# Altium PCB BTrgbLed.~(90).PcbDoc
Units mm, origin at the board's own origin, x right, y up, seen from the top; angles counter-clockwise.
Board outline 98.71 x 98.67 mm, 2 copper layers (Top Layer, Bottom Layer); 15 components, 12 nets, 66 pads, 7 vias.
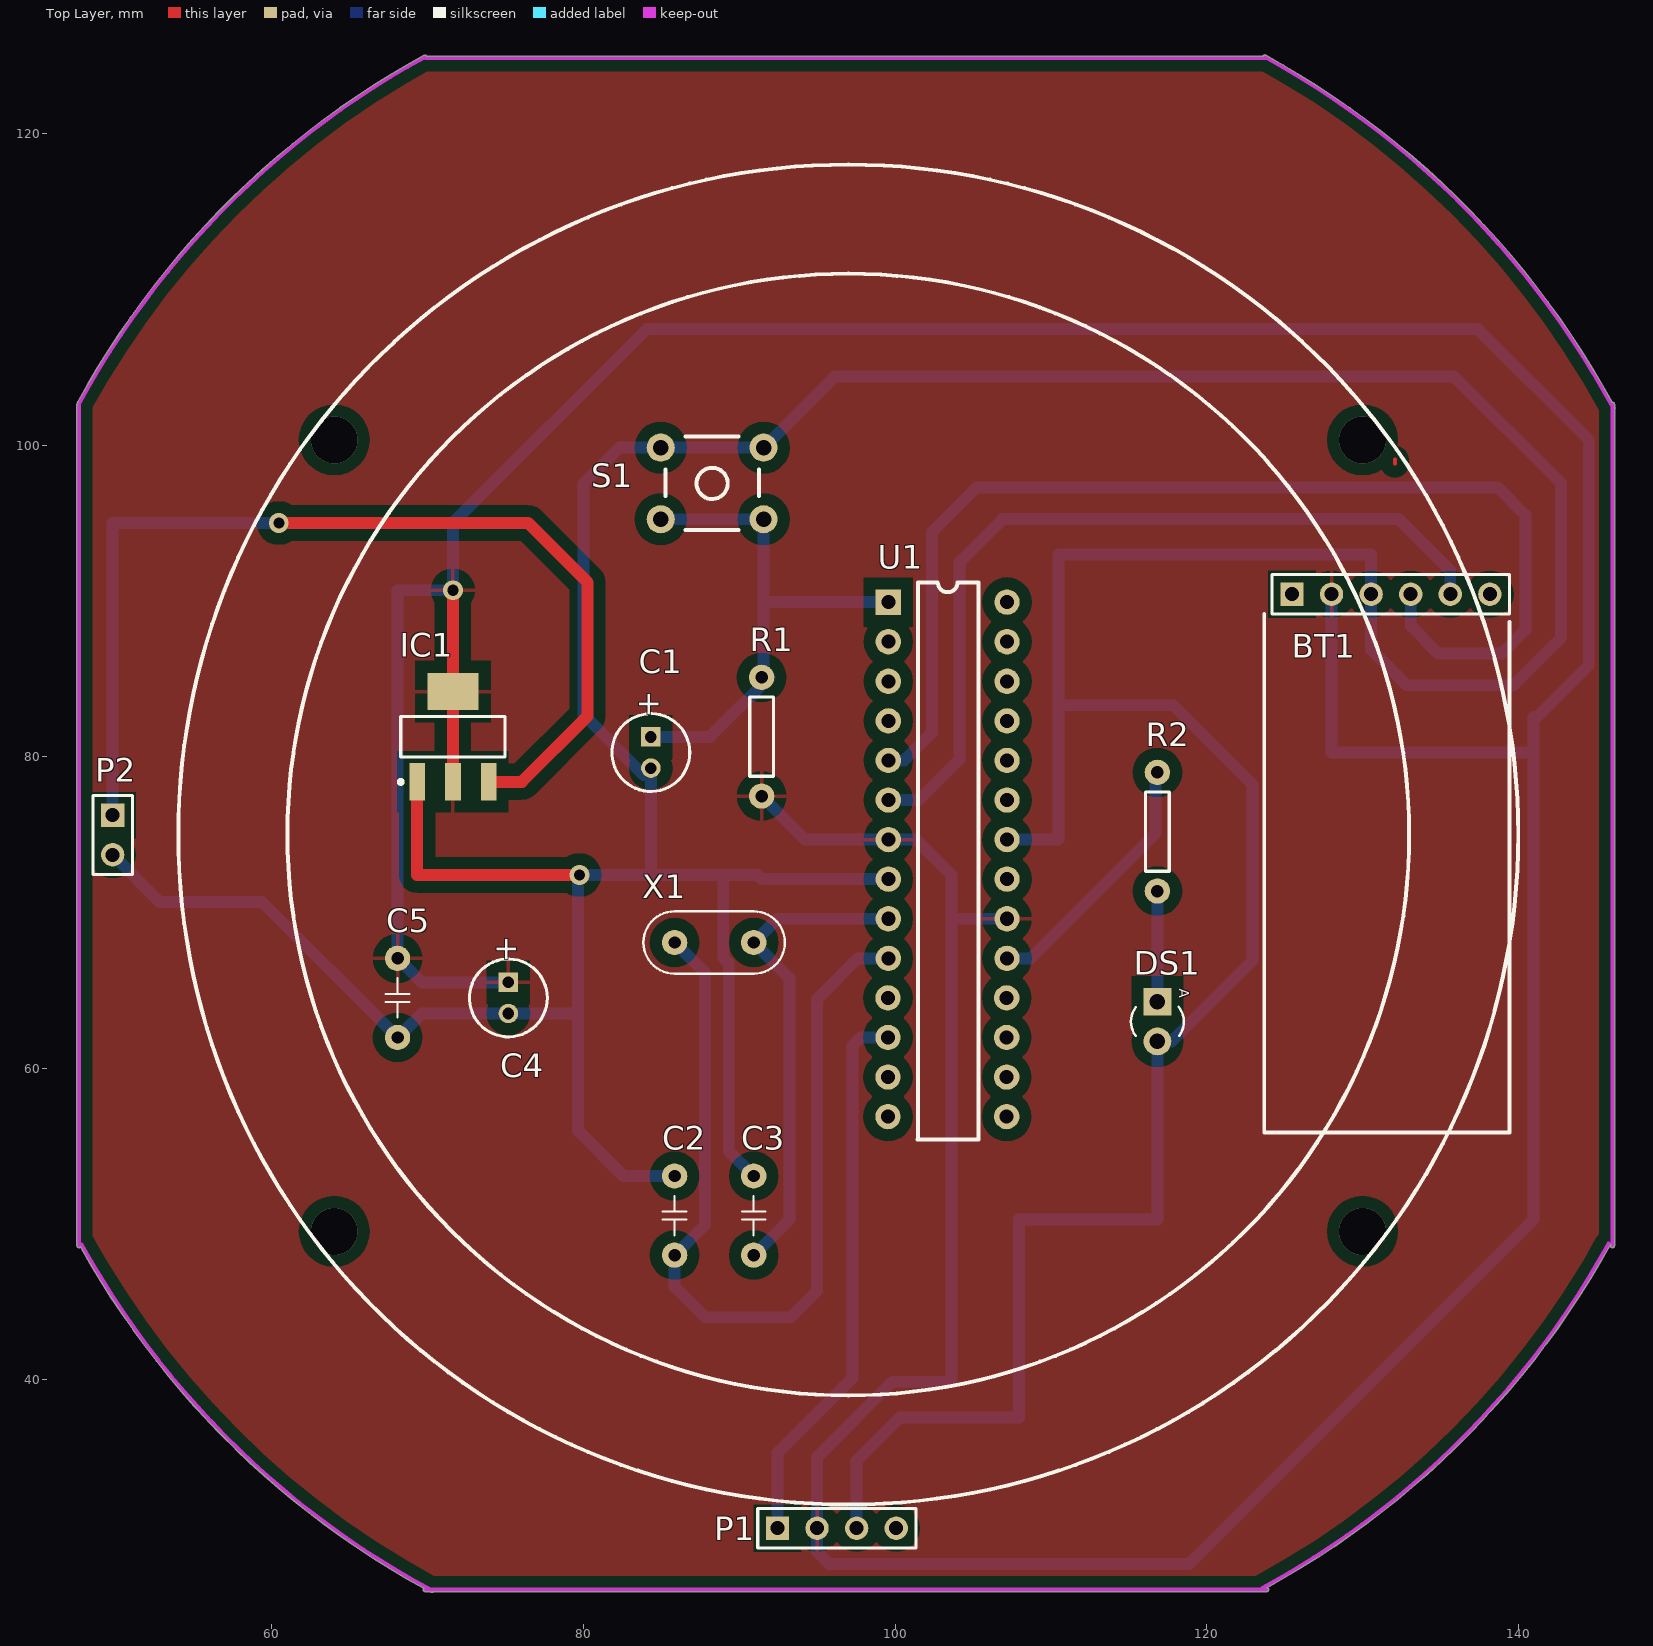
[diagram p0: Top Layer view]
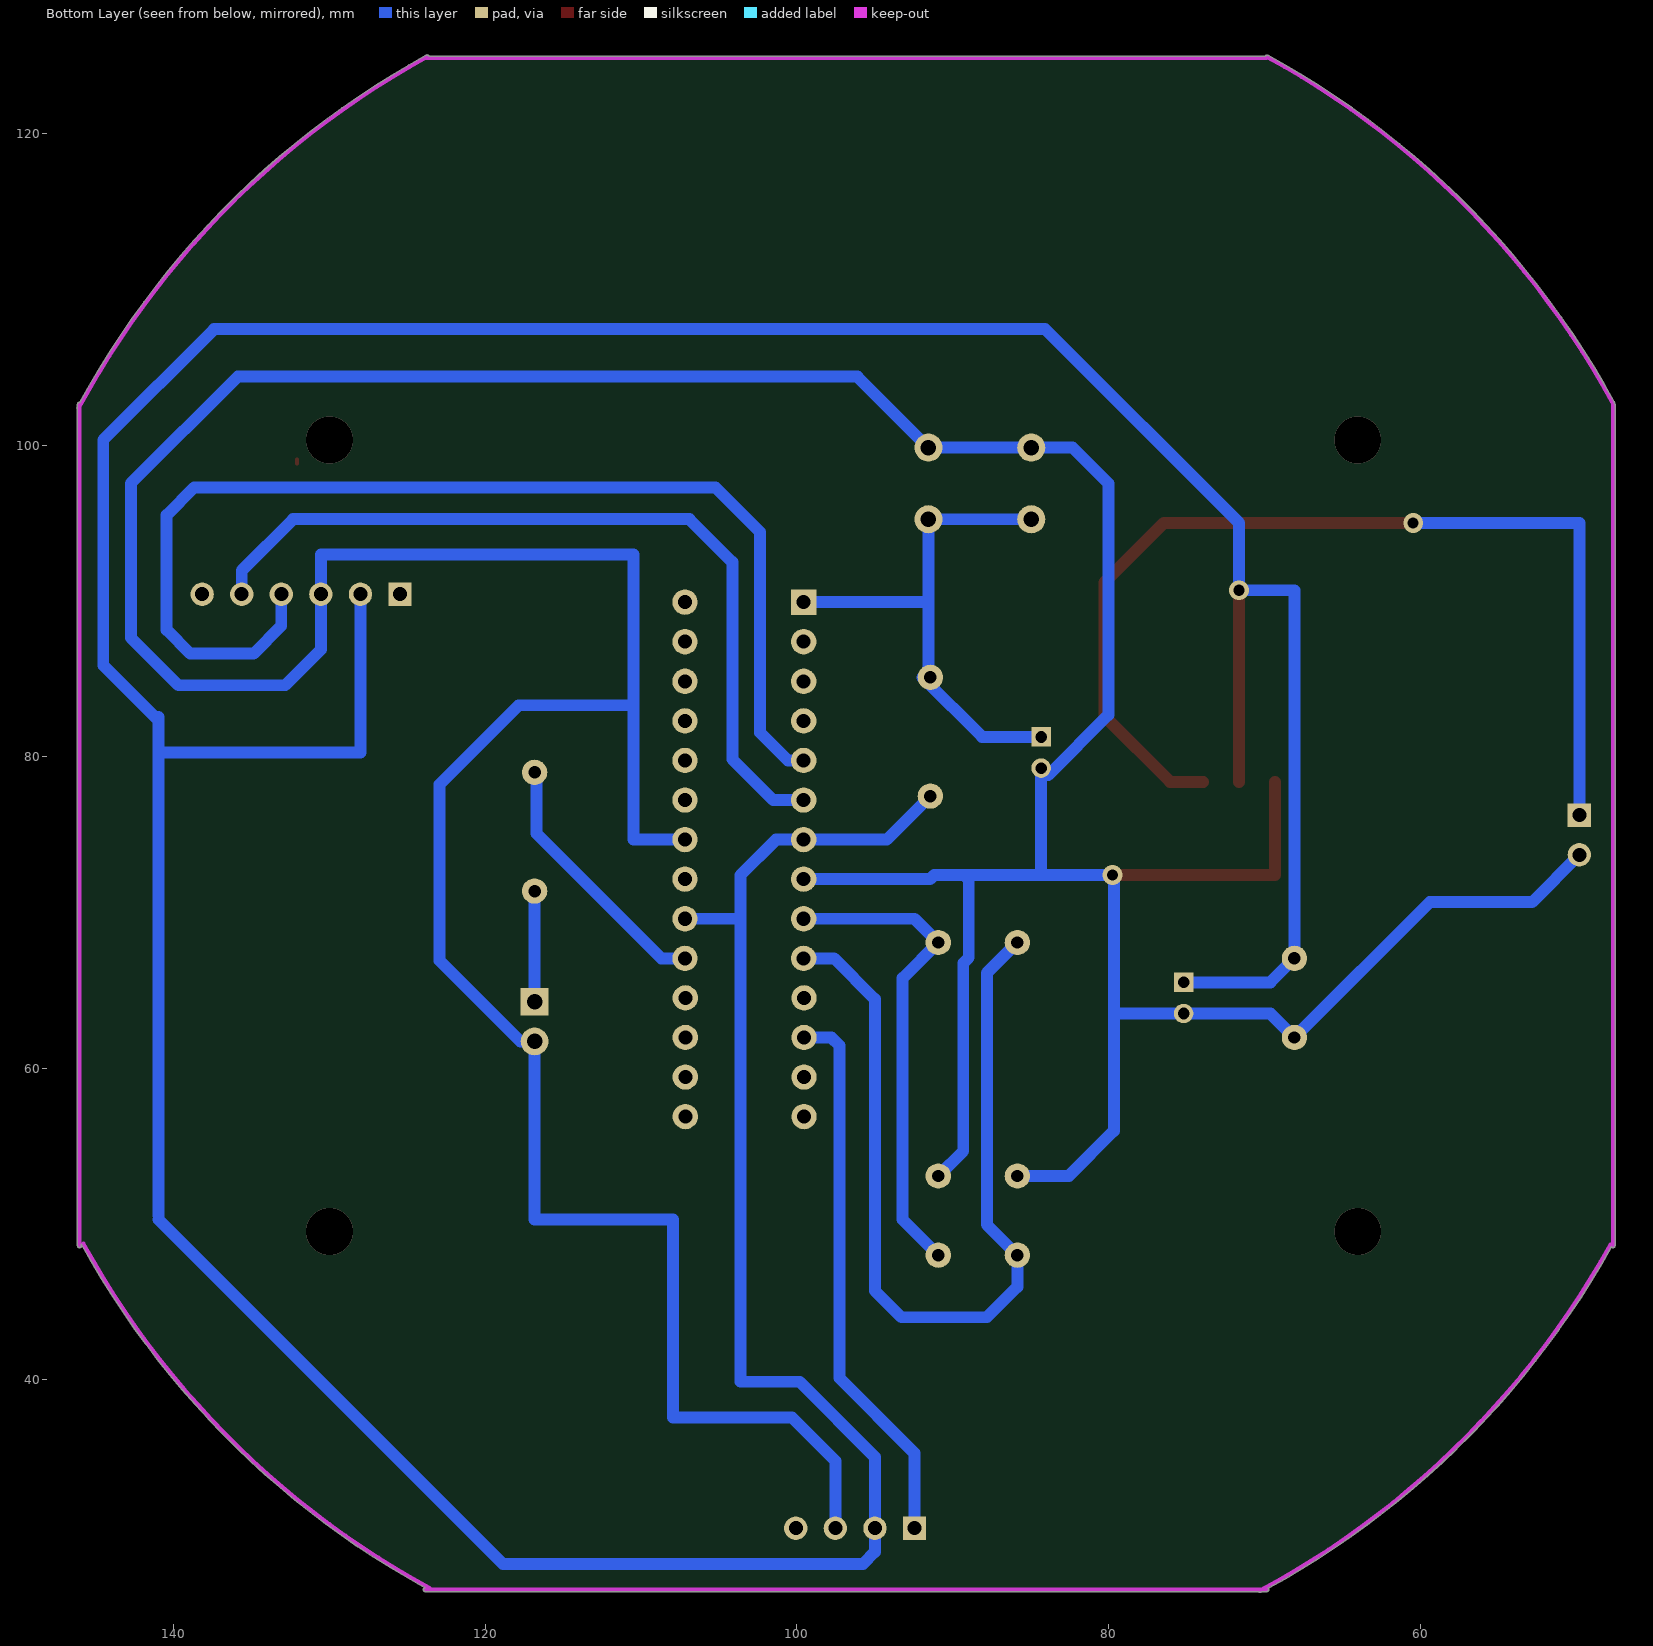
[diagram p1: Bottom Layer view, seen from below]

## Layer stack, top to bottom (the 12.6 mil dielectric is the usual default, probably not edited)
Top Layer: signal copper 0.0356
Dielectric: dielectric 0.32, FR-4, Dk 4.8
Bottom Layer: signal copper 0.0356

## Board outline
69.85,26.416 70.143,26.416 ccw(c96.781,75.819) 70.218,26.375 ccw(c70.279,26.487) 70.384,26.416 123.85,26.416 ccw(c123.85,26.543) 123.977,26.543 ccw(c123.85,26.543) 123.88,26.667 ccw(c96.781,75.819) 145.916,48.69 ccw(c145.805,48.751) 145.923,48.703 145.923,48.616 ccw(c146.05,48.616) 146.177,48.616 146.177,102.295 ccw(c146.082,102.379) 146.209,102.379 ccw(c146.082,102.379) 146.194,102.44 ccw(c96.781,75.819) 146.177,102.47 146.177,102.616 ccw(c146.05,102.616) 146.03,102.742 ccw(c96.781,75.819) 123.795,125.018 ccw(c123.734,124.906) 123.623,124.968 69.925,124.968 ccw(c69.817,124.9) 69.756,125.012 ccw(c96.781,75.819) 47.559,102.791 ccw(c47.671,102.73) 47.544,102.715 ccw(c47.625,102.616) 47.498,102.616 47.498,48.616 ccw(c47.625,48.616) 47.728,48.541 ccw(c96.781,75.819) 69.754,26.627 ccw(c69.85,26.543)

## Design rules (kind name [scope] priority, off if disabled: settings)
Clearance 舖銅安全間距 [All] p1: gap=0.762
Clearance [All] p2: gap=0.254
PolygonConnect [All] p1: connectstyle=Relief reliefconductorwidth=0.254 reliefentries=4 polygonreliefangle="90 Angle"
RoutingLayers [All] p1: top layer_v5=FALSE bottom layer_v5=TRUE
RoutingVias [All] p1: holewidth=0.711 width=1.27 viastyle="Through Hole" minholewidth=0.711 minwidth=1.27 maxholewidth=0.711 maxwidth=1.27
SilkscreenOverComponentPads [All] p1: minsilkscreentomaskgap=0.254
SolderMaskExpansion [All] p1: expansion=0.102
Width [All] p1: maxlimit=1.016 minlimit=0.508 preferedwidth=0.762
26 further rules are at their usual default settings.

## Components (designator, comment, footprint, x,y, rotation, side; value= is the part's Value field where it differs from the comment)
BT1 "Bluetooth" Bluetooth 125.476,90.424 r0 top
C1 "47uF" CAPPR2-5x6.8 84.328,80.264 r270 top
C2 "22pF" C200 85.852,50.546 r0 top
C3 "22pF" C200 90.932,50.546 r0 top
C4 "47uF" CAPPR2-5x6.8 75.184,64.516 r270 top
C5 "100pF" C200 68.072,64.516 r180 top
DS1 "TX-LED" LED-3mm_G 116.84,62.992 r270 top
IC1 "AM1117-5V" SOT-223 71.628,81.28 r90 top
P1 "環形LED燈" HDR1X4 92.456,30.48 r0 top
P2 "12V" HDR1X2 49.784,76.243 r270 top
R1 "10k" AXIAL-0.3 91.44,81.28 r90 top
R2 "220" AXIAL-0.3 116.84,75.184 r90 top
S1 "SW-PB" TACK6 88.263,97.536 r0 top
U1 "ATmega328" DIP-28 99.568,89.916 r270 top
X1 "16MHz" XTAL4-8 88.392,68.072 r180 top

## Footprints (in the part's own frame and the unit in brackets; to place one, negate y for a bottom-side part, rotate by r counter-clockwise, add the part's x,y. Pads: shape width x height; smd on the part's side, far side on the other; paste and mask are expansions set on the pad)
AXIAL-0.3 [mil] "0.3\" Resistor; 2 Leads"
  round 64 hole 31.5: 1(-150,0) 2(150,0)
  silkscreen extent -100,-30 100,30, body extent -161,-39 165,39, height 86
Bluetooth [mm]
  rect 1.5x1.5 hole 0.9: 1(0,0)
  round 1.5 hole 0.9: 2(2.54,0) 3(5.08,0) 4(7.62,0) 5(10.16,0) 6(12.7,0)
  silkscreen extent -1.27,-1.27 13.97,1.27, body extent -1.25,-1.3 13.97,1.28, height 11
C200 [mil] "塑膠電容器"
  round 64 hole 31.5: 1(0,100) 2(0,-100)
  silkscreen extent -30,-50 30,50, body extent -41,-136 39,135, height 354
CAPPR2-5x6.8 [mm] "Capacitor, Electrolytic, Radial; Body 5 x 6.8 mm (Dia.xH typ); Pin Spacing 2 mm (typ)"
  rect 1.25x1.25 hole 0.75: 1(-1,0)
  round 1.25 hole 0.75: 2(1,0)
  silkscreen extent -2.5,-2.5 2.5,2.5
DIP-28 [mil]
  rect 64x64 hole 35.43: 1(0,0)
  round 64 hole 35.43: 2(100,0) 3(200,0) 4(300,0) 5(400,0) 6(500,0) 7(600,0) 8(700,0) 9(800,0) 10(900,0) 11(1000,-0.79) 12(1100,-0.79) 13(1200,-0.79) 14(1300,-0.79) 15(1300,299.21) 16(1200,299.21) 17(1100,299.21) 18(1000,299.21) 19(900,300) 20(800,300) 21(700,300) 22(600,300) 23(500,300) 24(400,300) 25(300,300) 26(200,300) 27(100,300) 28(0,300)
  silkscreen extent -50,74 1358,228, body extent -53,-5 1358,304, height 209
HDR1X2 [mm] "Connector; Header; 2 Position"
  rect 1.5x1.5 hole 0.9: 1(0,0)
  round 1.5 hole 0.9: 2(2.54,0)
  silkscreen extent -1.27,-1.27 3.81,1.27
HDR1X4 [mm] "Connector; Header; 4 Position"
  rect 1.5x1.5 hole 0.9: 1(0,0)
  round 1.5 hole 0.9: 2(2.54,0) 3(5.08,0) 4(7.62,0)
  silkscreen extent -1.27,-1.27 8.89,1.27
LED-3mm_G [mil] "3mm LED_Green"
  rect 70x70 hole 39: 1(-50,0)
  round 70 hole 39: 2(50,0)
  silkscreen extent -38,-67 35,67, body extent -66,-68 67,66, height 181
SOT-223 [mm] "SOT223, 4-Leads, Body 6.7x7.3mm (max), Pitch 2.30mm, IPC Medium Density"
  rect 2.4x1 smd: 1(-2.9,2.3) 2(-2.9,0) 3(-2.9,-2.3)
  rect 2.4x3.3 smd: 2(2.9,0)
  silkscreen extent -3.02,-3.35 1.3,3.47, body extent -1.86,-3.35 1.86,3.35, height 1.8
TACK6 [mm]
  round 1.8 hole 1: 1(-3.3,2.3) 1(3.3,2.3) 2(-3.3,-2.3) 2(3.3,-2.3)
  silkscreen extent -3,-3 3,3, body extent -3,-3.01 3.08,3.04, height 8
XTAL4-8 [mil]
  round 64 hole 31.5: 1(-100,0) 2(100,0)
  silkscreen extent -179,-79 179,79, body extent -178,-80 192,79, height 157

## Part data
C1 C4: library part "Cap Pol1", "Polarized Capacitor (Radial)"
C2 C3 C5: library part Cap, "Capacitor"
DS1: library part LED, "Typical INFRARED GaAs LED"
IC1: library part AM1117
P1: library part "Header 4", "Header, 4-Pin"
P2: library part "Header 2", "Header, 2-Pin"
R1 R2: library part Res, "Resistor"
S1: "Switch"
U1: "Arduino"
X1: library part XTAL, "Crystal Oscillator"

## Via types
v1: diameter 3, hole 3, Top Layer to Bottom Layer, 4 vias
v2: diameter 1.27, hole 0.711, Top Layer to Bottom Layer, 3 vias

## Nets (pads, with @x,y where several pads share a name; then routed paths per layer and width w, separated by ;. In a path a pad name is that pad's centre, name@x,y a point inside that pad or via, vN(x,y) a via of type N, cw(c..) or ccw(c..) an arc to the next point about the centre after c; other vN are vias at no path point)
DI: P1.1 U1.12 | length 35.5
  Bottom Layer w0.762: P1.1 92.456,35.306 97.282,40.132 97.282,61.468 97.79,61.976 U1.12
DO: P1.4
GND: BT1.3 C1.2 C2.1 C3.1 C4.2 C5.1 DS1.2 IC1.1 P1.3 P2.2 S1.1 U1.8 U1.22 | length 366.4
  Top Layer w0.762: IC1.1 69.328,72.404 v2(79.742,72.404)
  Bottom Layer w0.762: P2.2 52.824,70.663 59.385,70.663 C5.1 69.612,63.516 C4.2 79.654,63.516 ; v2@79.654,72.404 79.654,63.516 ; v2(79.742,72.404) 91.188,72.404 91.456,72.136 U1.8 ; 84.328,72.658 C1.2 83.875,78.812 80.01,82.677 80.01,97.536 82.31,99.836 84.963,99.836 91.563,99.836 96.121,104.394 135.89,104.394 142.748,97.536 142.748,87.63 139.7,84.582 132.842,84.582 130.556,86.868 130.556,92.964 110.49,92.964 110.49,74.676 U1.22 ; C2.1 82.55,53.086 79.654,55.982 79.654,63.516 ; 89.154,72.302 88.976,72.125 88.976,67.103 89.332,66.747 89.332,54.686 C3.1 ; P1.3 97.536,34.798 100.33,37.592 107.95,37.592 107.95,50.292 116.84,50.292 DS1.2 117.754,61.722 122.936,66.904 122.936,78.232 117.869,83.299 110.731,83.299
NetC1_1: C1.1 R1.2 S1.2 U1.1 | length 33.8
  Bottom Layer w0.762: C1.1 88.122,81.264 R1.2@91.948,85.09 ; S1.2@84.963,95.236 91.563,95.236 91.563,89.916 ; R1.2@91.563,85.213 91.563,89.916 ; U1.1 91.563,89.916
NetC2_2: C2.2 U1.10 X1.2 | length 58.8
  Bottom Layer w0.762: X1.2 87.808,66.116 87.808,49.962 C2.2 85.852,45.974 87.808,44.018 93.294,44.018 94.996,45.72 94.996,64.44 97.612,67.056 U1.10
NetC3_2: C3.2 U1.9 X1.1 | length 31.2
  Bottom Layer w0.762: C3.2 93.218,50.292 93.218,65.786 X1.1 92.456,69.596 U1.9
NetDS1_1: DS1.1 R2.1 | length 7.1
  Bottom Layer w0.762: DS1.1 R2.1
NetIC1_3: IC1.3 P2.1 | length 67.5
  Top Layer w0.762: v2@60.706,94.996 76.454,94.996 80.264,91.186 80.264,82.592 76.052,78.38 IC1.3
  Bottom Layer w0.762: P2.1@50.081,76.243 P2.1 49.784,94.996 v2(60.452,94.996)
NetR2_2: R2.2 U1.19 | length 16.8
  Bottom Layer w0.762: U1.19 108.712,67.056 116.726,75.07 116.726,78.88 R2.2
RX: BT1.5 U1.6 | length 53.8
  Bottom Layer w0.762: U1.6 101.524,77.216 104.14,79.832 104.14,92.481 106.909,95.25 132.334,95.25 135.636,91.948 BT1.5
TX: BT1.4 U1.5 | length 74.6
  Bottom Layer w0.762: U1.5 100.584,79.756 102.362,81.534 102.362,94.412 105.232,97.282 138.684,97.282 140.462,95.504 140.462,88.138 138.938,86.614 134.874,86.614 133.096,88.392 BT1.4
VCC: BT1.2 C4.1 C5.2 IC1.2 P1.2 R1.1 U1.7 U1.20 | length 329.5
  Top Layer w0.762: IC1.2@71.628,78.38 71.628,84.18 v2(71.628,90.678)
  Bottom Layer w0.762: C4.1 69.612,65.516 C5.2 68.072,90.678 v2(71.628,90.678) 71.628,94.996 84.074,107.442 137.414,107.442 144.526,100.33 144.526,85.852 140.97,82.296 ; R1.1 94.234,74.676 U1.7 101.346,74.676 103.632,72.39 103.632,69.596 ; U1.20 103.632,69.596 ; BT1.2 128.016,80.264 140.716,80.264 ; 140.97,50.292 118.872,28.194 95.758,28.194 94.996,28.956 P1.2 94.996,35.052 99.822,39.878 103.632,39.878 103.632,69.596 ; 140.97,50.546 140.97,82.55
pads on no net: BT1.1 BT1.6 U1.2 U1.3 U1.4 U1.11 U1.13 U1.14 U1.15 U1.16 U1.17 U1.18 U1.21 U1.23 U1.24 U1.25 U1.26 U1.27 U1.28
copper on no net: | length 0.3
  Top Layer w0.254: 132.08,98.806 132.08,99.06
  other v1: 64.008,49.53 130.008,49.53 64.008,100.33 130.008,100.33

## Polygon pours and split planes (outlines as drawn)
VCC on Top Layer "Top Layer-No Net" (solid): 47.599,48.616 47.646,48.601 47.817,48.59 ccw(c96.781,75.819) 69.474,26.899 124.088,26.899 ccw(c96.781,75.819) 145.827,48.739 145.828,48.739 145.829,48.741 146.024,48.703 146.024,48.616 146.076,48.616 146.076,102.295 146.101,102.362 146.108,102.379 146.104,102.391 146.088,102.422 146.076,102.47 146.076,102.616 146.046,102.642 146.046,102.641 145.941,102.693 ccw(c96.781,75.819) 123.746,124.929 123.711,124.919 123.623,124.867 69.925,124.867 69.839,124.914 69.805,124.923 ccw(c96.781,75.819) 47.648,102.742 47.645,102.727 47.646,102.715 47.609,102.636 47.608,102.636 47.599,102.616

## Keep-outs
Keep-Out Layer:
  lines w0.254: 47.625,48.616 47.625,102.616 ; 47.671,102.73 cw(c96.781,75.819) 69.817,124.9 ; 47.783,48.704 ccw(c96.781,75.819) 70.279,26.487 ; 69.85,26.543 123.85,26.543 ; 69.85,124.841 123.85,124.841 ; 123.584,26.65 ccw(c96.781,75.819) 145.805,48.751 ; 123.734,124.906 cw(c96.781,75.819) 146.082,102.379 ; 146.05,48.616 146.05,102.616

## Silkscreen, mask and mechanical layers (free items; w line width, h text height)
Top Overlay:
  circle w0.254: c97,75 r43
  circle w0.254: c97,75 r36
  lines w0.254: 123.698,89.154 123.698,55.88 139.446,55.88 139.446,88.646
